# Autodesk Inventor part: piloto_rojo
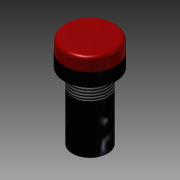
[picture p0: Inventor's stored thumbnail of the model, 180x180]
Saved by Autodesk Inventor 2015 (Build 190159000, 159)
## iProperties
Created: 2016-04
Part Number: piloto_rojo
Material: Genérico
Document SubType Name: Modeling
Designer: Diego
Density: 1 g/cm^3
Appearance: Valor por defecto
Author: Diego
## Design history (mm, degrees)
sketch "Boceto1"
  geometry: C1 r 14.5 at (0, 0); 1 further point
  constraints: 1 centre point, 1 coincident
  dimensions: "d0" = 29 diameter of C1
extrude "Extrusión1" new body sketch "Boceto1" distance "d1" = 7.5; taper "d2" = 0 deg
sketch "Boceto2"
  geometry: C1 r 14.6 at (0, 0); 1 further point
  constraints: 1 centre point, 1 coincident
  dimensions: "d3" = 29.2 diameter of C1
extrude "Extrusión2" join sketch "Boceto2" distance "d4" = 7.5; taper "d5" = 0 deg
sketch "Boceto3"
  geometry: C1 r 10 at (0, 0); 1 further point
  constraints: 1 centre point, 1 coincident
  dimensions: "d6" = 20 diameter of C1
extrude "Extrusión3" join sketch "Boceto3" distance "d7" = 10; taper "d8" = 0 deg
feature "Rosca1" dims "d9" = 10, "d10" = 0
sketch "Boceto4"
  geometry: C1 r 10 at (0, 0) reference; C2 r 9.95 at (0, 0); 1 further point
  constraints: 1 centre point, 1 coincident
  dimensions: "d11" = 19.9 diameter of C2
extrude "Extrusión4" join sketch "Boceto4" distance "d12" = 28; taper "d13" = 0 deg
sketch "Boceto5"
  geometry: C1 r 2.5 at (-5, 0); C2 r 2.5 at (5, 0); 1 further point
  constraints: 2 centre point
  dimensions: "d14" = 5 diameter of C1; "d15" = 5 diameter of C2
extrude "Extrusión5" cut sketch "Boceto5" distance "d16" = 5; taper "d17" = 0 deg
fillet "Empalme1" dims "d18" = 2
node "Sólido1"
